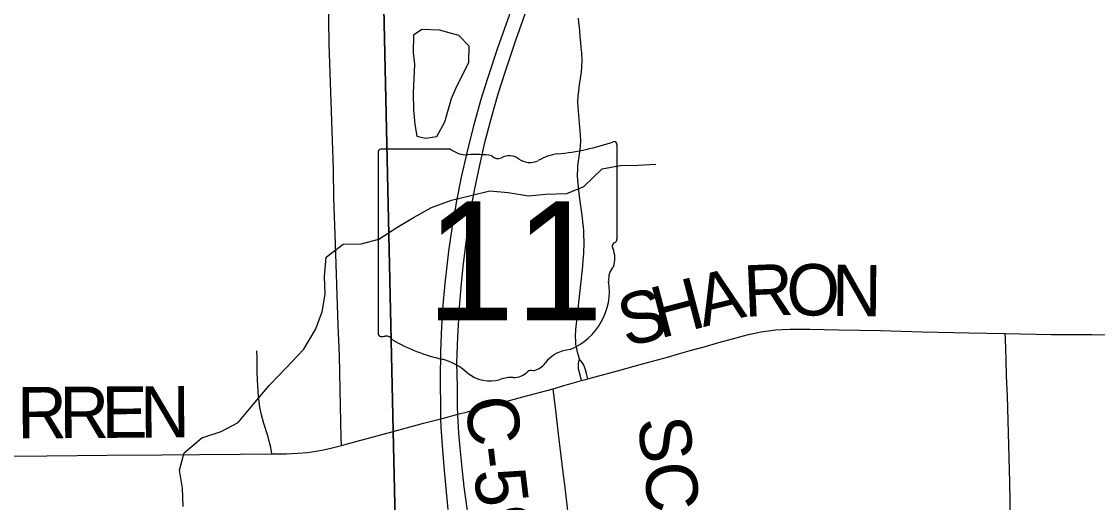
# Model space of a CAD drawing. Extents: x -6.4 to 34, y -4.2 to 22.
# Drawn here: x 6.594 to 7.783, y 18.167 to 18.698 of the extents above; entities that cross this region are included whole.
import ezdxf

# ---------------------------------------------------------------- set-up
doc = ezdxf.new("R2010")
doc.units = 0
for name, color, linetype in [('GM_X_Corporation', 7, 'Continuous'), ('GM_X_County_Road', 7, 'Continuous'), ('GM_X_County_Road_Text', 7, 'Continuous'), ('GM_X_Minor_Lake', 7, 'Continuous'), ('GM_X_Minor_River', 7, 'Continuous'), ('GM_X_State_Location', 7, 'Continuous'), ('GM_X_State_Route', 7, 'Continuous'), ('GM_X_State_Shield', 7, 'Continuous'), ('GM_X_Township_Road', 7, 'Continuous')]:
    doc.layers.add(name, color=color, linetype=linetype)

msp = doc.modelspace()

# ---------------------------------------------------------------- linework, layer by layer
at = {"layer": 'GM_X_Corporation'}
for points in [[(7.0556, 16.0421), (7.0203, 17.4801), (7.0196, 17.5362), (7.0186, 17.6104), (7.0181, 17.6534), (7.0176, 17.6906), (7.0048, 18.2458), (6.9894, 18.9467)], [(6.9894, 18.9467), (7.0048, 18.2458), (7.0176, 17.6906), (7.0181, 17.6534), (7.0186, 17.6104), (7.0196, 17.5362), (7.0203, 17.4801), (7.0556, 16.0421)]]:
    msp.add_lwpolyline(points, dxfattribs=at)
at = {"layer": 'GM_X_County_Road'}
for points in [[(7.1949, 18.2963), (7.2129, 18.3015), (7.2148, 18.302), (7.22, 18.3034), (7.2281, 18.3055), (7.2526, 18.3123), (7.2801, 18.3201), (7.3078, 18.3274), (7.3199, 18.3309), (7.3328, 18.3346), (7.3482, 18.3389), (7.3645, 18.3436), (7.3837, 18.3489), (7.3903, 18.3505), (7.3987, 18.3527), (7.4042, 18.3538), (7.4108, 18.3553), (7.4193, 18.3566), (7.4273, 18.3575), (7.4346, 18.3581), (7.4433, 18.3582), (7.4525, 18.3583), (7.4649, 18.3582), (7.4966, 18.3574), (7.5432, 18.3567), (7.5891, 18.3554), (7.6412, 18.3543), (7.6807, 18.3535), (7.7316, 18.3525), (7.7763, 18.3524), (7.8503, 18.3515)], [(7.6878, 18.0853), (7.6858, 18.1891), (7.6832, 18.2848), (7.6824, 18.3065), (7.6818, 18.3252), (7.681, 18.3472), (7.6807, 18.3535)], [(7.088, 18.2673), (7.1146, 18.2744), (7.1482, 18.2835), (7.1816, 18.2924), (7.1949, 18.2963)], [(7.262, 17.7953), (7.2583, 17.8123), (7.2528, 17.8387), (7.2487, 17.8585), (7.2368, 17.9145), (7.2331, 17.9317), (7.23, 17.9461), (7.2262, 17.9644), (7.2225, 17.9823), (7.2195, 17.9966), (7.2171, 18.0088), (7.2149, 18.0229), (7.2122, 18.0423), (7.2106, 18.0543), (7.2067, 18.087), (7.2035, 18.1117), (7.1994, 18.145), (7.1972, 18.1641), (7.1948, 18.1833), (7.1924, 18.203), (7.1905, 18.2184), (7.1872, 18.2456), (7.1849, 18.2654), (7.1816, 18.2924)], [(7.0384, 18.2543), (7.0577, 18.2593), (7.0606, 18.2601), (7.0763, 18.2642), (7.087, 18.267), (7.088, 18.2673)], [(7.005, 18.2452), (7.0317, 18.2525), (7.0384, 18.2543)], [(6.9477, 18.2298), (6.9652, 18.2344), (7.005, 18.2452)], [(6.8928, 18.2209), (6.8998, 18.2211), (6.9102, 18.222), (6.92, 18.2233), (6.9279, 18.2248), (6.9376, 18.2271), (6.9477, 18.2298)], [(6.5604, 18.2179), (6.6226, 18.2185), (6.6891, 18.2192), (6.7494, 18.2194), (6.791, 18.2199), (6.8358, 18.2202), (6.8709, 18.2205), (6.8867, 18.2207), (6.8928, 18.2209)]]:
    msp.add_lwpolyline(points, dxfattribs=at)
at = {"layer": 'GM_X_Minor_Lake'}
msp.add_line((7.0283, 18.6513), (7.0269, 18.6194), dxfattribs=at)
msp.add_lwpolyline([(7.0269, 18.6194), (7.0272, 18.6008), (7.029, 18.5844), (7.0312, 18.5715), (7.0406, 18.5695), (7.0531, 18.5714), (7.062, 18.5873), (7.0693, 18.6131), (7.0751, 18.6267), (7.0885, 18.6529), (7.089, 18.6711), (7.0773, 18.683), (7.0562, 18.6887), (7.0365, 18.6896), (7.0274, 18.6832), (7.0269, 18.6642), (7.0283, 18.6513)], dxfattribs=at)
at = {"layer": 'GM_X_Minor_River'}
msp.add_lwpolyline([(6.773, 18.1625), (6.7724, 18.1826), (6.7691, 18.2024), (6.7741, 18.2217), (6.7936, 18.2383), (6.8148, 18.2451), (6.8338, 18.2553), (6.8502, 18.2749), (6.8678, 18.2961), (6.8868, 18.3154), (6.9063, 18.3362), (6.9193, 18.3578), (6.9266, 18.3775), (6.9297, 18.3969), (6.9291, 18.4166), (6.9308, 18.4379), (6.9498, 18.4522), (6.9695, 18.4525), (6.9892, 18.4577), (7.009, 18.4706), (7.028, 18.4822), (7.0473, 18.4928), (7.0694, 18.501), (7.0906, 18.5059), (7.1118, 18.5111), (7.1319, 18.5095), (7.1542, 18.5056), (7.1735, 18.5074), (7.1966, 18.5084), (7.2156, 18.5159), (7.2358, 18.5356), (7.2555, 18.5393), (7.2756, 18.5396), (7.2949, 18.5406)], dxfattribs=at)
at = {"layer": 'GM_X_State_Route'}
for points in [[(7.0764, 18.2632), (7.0763, 18.2642), (7.0759, 18.2716), (7.0759, 18.2948), (7.0753, 18.3211), (7.0763, 18.3498), (7.078, 18.3821), (7.0802, 18.4093), (7.0825, 18.431), (7.0861, 18.46), (7.0901, 18.4865), (7.095, 18.5134), (7.1005, 18.5396), (7.1063, 18.5645), (7.1134, 18.5922), (7.121, 18.6185), (7.1285, 18.6422), (7.1405, 18.6776), (7.1852, 18.8048)], [(7.0658, 18.159), (7.0619, 18.1982), (7.06, 18.2199), (7.058, 18.25), (7.0577, 18.2593), (7.0574, 18.2685), (7.0571, 18.3034), (7.0575, 18.3337), (7.0586, 18.3613), (7.0598, 18.3808), (7.0622, 18.4086), (7.0664, 18.4444), (7.0704, 18.472), (7.0753, 18.5002), (7.0805, 18.5264), (7.0865, 18.5531), (7.0943, 18.5844), (7.1021, 18.6125), (7.1093, 18.6357), (7.1209, 18.6704), (7.1444, 18.7366)], [(7.1081, 18.0394), (7.1054, 18.0556), (7.0967, 18.1035), (7.0885, 18.1492), (7.0867, 18.16), (7.0834, 18.1839), (7.0814, 18.2015), (7.0788, 18.2272), (7.0775, 18.2435), (7.0764, 18.2632)]]:
    msp.add_lwpolyline(points, dxfattribs=at)
at = {"layer": 'GM_X_State_Shield'}
for p, q in [((7.2521, 18.4576), (7.2521, 18.5623)), ((6.9884, 18.5539), (6.9884, 18.3538)), ((7.0682, 18.5573), (6.991, 18.5573)), ((7.252, 18.4576), (7.2521, 18.4576))]:
    msp.add_line(p, q, dxfattribs=at)
for centre, radius, start, end in [((7.1581, 18.8301), 0.2796, 275.8445, 288.9065), ((7.2491, 18.5627), 0.00294, 351.8621, 97.738), ((6.9914, 18.5543), 0.00305, 98.1301, 188.1301), ((7.0866, 18.5805), 0.0296, 231.6195, 271.1119), ((7.0964, 18.445), 0.1064, 80.4867, 94.9883), ((7.1206, 18.5553), 0.00855, 219.7921, 297.1024), ((7.1331, 18.5322), 0.0178, 54.4667, 119.1411), ((7.1938, 18.4962), 0.0563, 97.3462, 120.7689), ((7.1561, 18.5639), 0.0214, 233.8562, 294.8282), ((7.2514, 18.4499), 0.00454, 107.944, 210.337), ((7.2489, 18.4572), 0.00314, 289.6038, 7.7341), ((7.2225, 18.4367), 0.0273, 340.033, 23.6496), ((7.2626, 18.4138), 0.0198, 136.8065, 186.9296), ((7.1738, 18.4005), 0.0699, 292.3089, 8.9858), ((6.9915, 18.3533), 0.00308, 171.9584, 258.3066), ((6.9919, 18.3738), 0.0235, 267.339, 280.6039), ((6.9967, 18.3422), 0.00848, 29.7484, 93.2717), ((7.1038, 18.522), 0.2019, 240.4129, 257.1985), ((7.2033, 18.2976), 0.0383, 94.4031, 142.5768), ((7.0436, 18.2638), 0.0632, 47.1842, 75.836), ((7.138, 18.3262), 0.0214, 268.777, 315.5493), ((7.1573, 18.3068), 0.00601, 65.7517, 132.6484), ((7.1548, 18.3344), 0.0226, 282.8732, 323.2771), ((7.1119, 18.3412), 0.0401, 230.7004, 286.2918), ((7.1351, 18.272), 0.0329, 85.6951, 111.2099)]:
    msp.add_arc(centre, radius, start, end, dxfattribs=at)
at = {"layer": 'GM_X_Township_Road'}
for points in [[(6.9477, 18.2298), (6.9475, 18.2384), (6.9468, 18.2736), (6.9455, 18.329), (6.9442, 18.3626), (6.9414, 18.4527), (6.9395, 18.5034), (6.9389, 18.5348), (6.9343, 18.6736), (6.9331, 18.7498)], [(7.22, 18.3034), (7.2188, 18.3079), (7.2172, 18.3134), (7.2163, 18.3168), (7.2154, 18.3187), (7.2144, 18.3204), (7.2127, 18.3229), (7.2107, 18.325), (7.2096, 18.3291), (7.2085, 18.3328), (7.2077, 18.337), (7.2068, 18.3413), (7.2065, 18.345), (7.2063, 18.3506), (7.2067, 18.3581), (7.2083, 18.3742), (7.2142, 18.4279), (7.2148, 18.4346), (7.2154, 18.4416), (7.2156, 18.4457), (7.2158, 18.4503), (7.2157, 18.4558), (7.2156, 18.4614), (7.2153, 18.467), (7.2151, 18.4714), (7.2145, 18.4765), (7.214, 18.4813), (7.2107, 18.5053), (7.21, 18.5114), (7.2095, 18.5167), (7.2089, 18.522), (7.2085, 18.5288), (7.2087, 18.535), (7.209, 18.5384), (7.2093, 18.5418), (7.2105, 18.5491), (7.2112, 18.5541), (7.2118, 18.5603), (7.212, 18.5665), (7.2117, 18.5727), (7.2091, 18.6037), (7.2089, 18.6092), (7.2092, 18.6161), (7.2098, 18.6213), (7.2102, 18.6253), (7.211, 18.6308), (7.2117, 18.6348), (7.2122, 18.6384), (7.2128, 18.6419), (7.2134, 18.6487), (7.2135, 18.6549), (7.2132, 18.6636), (7.2126, 18.6696), (7.2121, 18.6751), (7.2116, 18.6815), (7.211, 18.6881), (7.2106, 18.6921), (7.2101, 18.6973), (7.2097, 18.702)], [(6.8709, 18.2205), (6.8698, 18.2277), (6.8688, 18.2315), (6.8669, 18.2394), (6.8622, 18.2542), (6.8595, 18.2638), (6.8578, 18.2716), (6.8568, 18.2783), (6.8559, 18.2882), (6.8554, 18.2974), (6.8552, 18.3005), (6.8548, 18.3123), (6.8547, 18.3194), (6.8546, 18.3274), (6.8543, 18.3342)], [(7.2129, 18.3015), (7.2113, 18.3077), (7.2097, 18.3146), (7.2094, 18.3172), (7.2095, 18.3196), (7.2099, 18.3223), (7.2107, 18.325)]]:
    msp.add_lwpolyline(points, dxfattribs=at)

# ---------------------------------------------------------------- texts
at = {"layer": 'GM_X_County_Road_Text'}
for s, height, rotation, p in [('R', 0.0568, 2.5202, (7.393, 18.3719)), ('O', 0.0568, 358.9235, (7.4387, 18.374)), ('N', 0.0568, 359.4012, (7.4892, 18.373)), ('A', 0.0568, 13.6917, (7.3473, 18.3605)), ('H', 0.0568, 14.7669, (7.2993, 18.3478)), ('S', 0.0568, 14.7842, (7.2622, 18.3381)), ('R', 0.0568, 0.3957, (6.5898, 18.2375)), ('R', 0.0568, 0.3961, (6.6365, 18.2378)), ('E', 0.0568, 0.3961, (6.6831, 18.2381)), ('N', 0.0568, 0.3971, (6.7256, 18.2384)), ('C-590', 0.05682, 276.9199, (7.0841, 18.2812)), ('SCOVILLE', 0.05682, 277.2662, (7.2745, 18.2583))]:
    msp.add_text(s, height=height, rotation=rotation, dxfattribs=at).set_placement(p)
at = {"layer": 'GM_X_State_Location'}
for s in ['s', 'r']:
    msp.add_text(s, height=0.000189, dxfattribs=at).set_placement((7.1173, 18.4405))
msp.add_text('11', height=0.000189, rotation=0, dxfattribs=at).set_placement((7.0696, 18.4267))
at = {"layer": 'GM_X_State_Shield'}
msp.add_text('11', height=0.13184, dxfattribs=at).set_placement((7.0411, 18.3679))

doc.saveas('drawing.dxf')
